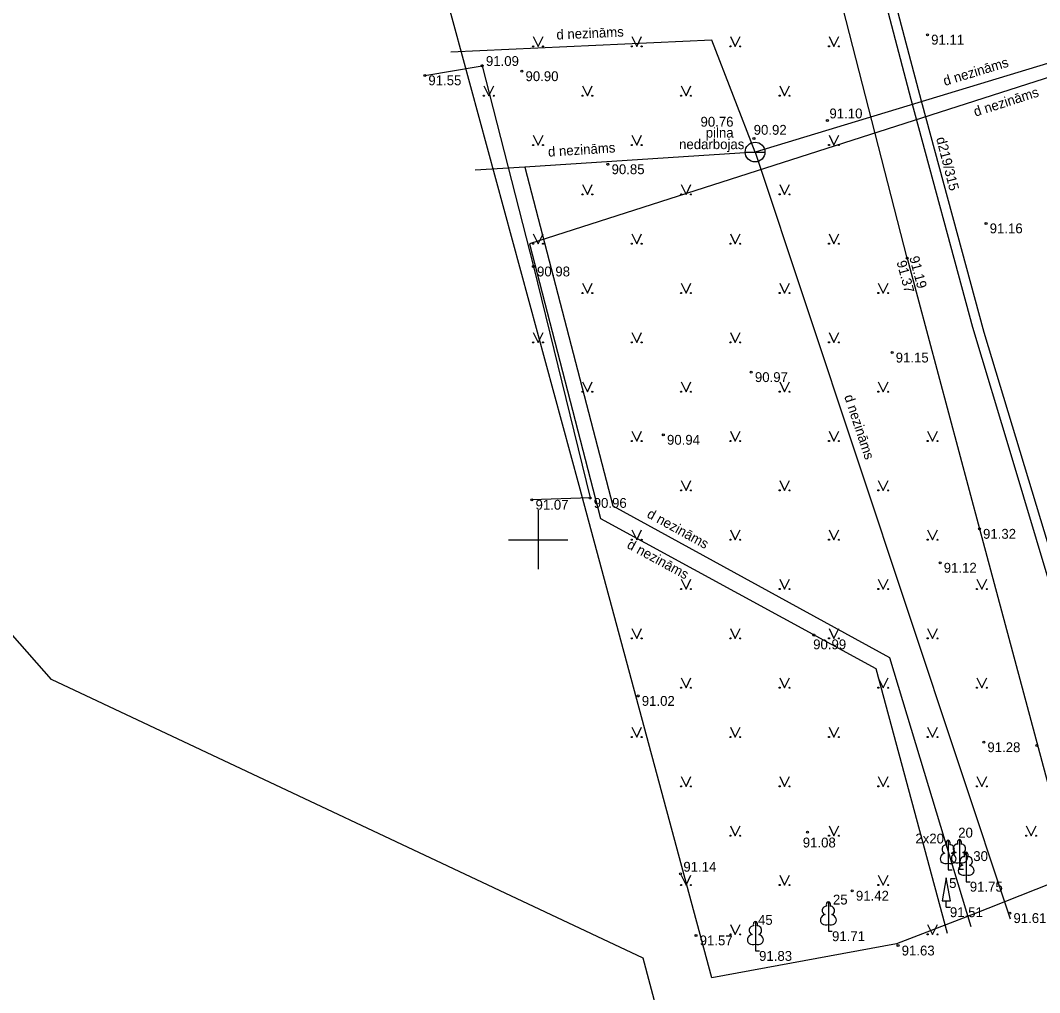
# Model space of a CAD drawing. Extents: x 634272 to 634544, y 247463 to 247653.
# Drawn here: x 634323.8 to 634375.4, y 247527 to 247576.3 of the extents above; entities that cross this region are included whole.
import ezdxf

# ---------------------------------------------------------------- set-up
doc = ezdxf.new("R2010")
doc.units = 0
for name, color, linetype in [('CELI_CAPM_####_####_#', 7, 'Continuous'), ('GEOD_ELEM_####_####_#', 7, 'Continuous'), ('NORB_ZOGS_ZSTP_####_#', 7, 'Continuous'), ('RAMI_UZMR_####_####_#', 7, 'Continuous'), ('RELJ_AATZ_####_TKST_#', 7, 'Continuous'), ('RELJ_ELEM_####_####_#', 7, 'Continuous'), ('ROBZ_PROJ_####_####_#', 7, 'Continuous'), ('SILT_VADP_UDEN_####_#', 7, 'Continuous'), ('SILT_VADP_UDEN_TKST_#', 7, 'Continuous'), ('TERT_DIAM_####_TKST_#', 7, 'Continuous'), ('TERT_ELEM_####_####_#', 7, 'Continuous'), ('UDTK_ELEM_####_####_#', 7, 'Continuous'), ('UDTK_ELEM_####_TKST_#', 7, 'Continuous'), ('UDTK_VADP_NEDR_####_#', 7, 'Continuous'), ('UDTK_VADP_NEDR_TKST_#', 7, 'Continuous')]:
    doc.layers.add(name, color=color, linetype=linetype)

msp = doc.modelspace()

# ---------------------------------------------------------------- linework, layer by layer
at = {"layer": 'CELI_CAPM_####_####_#'}
for points in [[(634368.714, 247564.266), (634363.359, 247585.148)], [(634368.714, 247564.266), (634372.374, 247550.548), (634376.283, 247536.001), (634382.231, 247537.822), (634388.468, 247539.583)]]:
    msp.add_lwpolyline(points, dxfattribs=at)
at = {"layer": 'GEOD_ELEM_####_####_#'}
for p, q in [((634350, 247551.5), (634350, 247550)), ((634348.5, 247550), (634350, 247550)), ((634350, 247550), (634350, 247548.5)), ((634350, 247550), (634351.5, 247550))]:
    msp.add_line(p, q, dxfattribs=at)
at = {"layer": 'NORB_ZOGS_ZSTP_####_#'}
msp.add_lwpolyline([(634344.251, 247573.53), (634347.163, 247574.022), (634349.76, 247563.843), (634352.634, 247552.114), (634349.684, 247552.021)], dxfattribs=at)
at = {"layer": 'RAMI_UZMR_####_####_#'}
msp.add_lwpolyline([(634376.048, 247532.596), (634371.988, 247530.992), (634368.176, 247529.515), (634358.81, 247527.799), (634352.082, 247552.749), (634342.787, 247586.946)], dxfattribs=at)
at = {"layer": 'RELJ_ELEM_####_####_#'}
for centre in [(634369.743, 247575.59), (634347.163, 247574.022), (634349.176, 247573.739), (634344.251, 247573.53), (634364.666, 247571.247), (634360.946, 247570.338), (634353.54, 247569.024), (634372.711, 247566.027), (634368.714, 247564.266), (634349.76, 247563.843), (634367.946, 247559.481), (634360.808, 247558.49), (634356.35, 247555.313), (634349.684, 247552.021), (634352.634, 247552.114), (634372.374, 247550.548), (634370.382, 247548.828), (634363.979, 247545.17), (634355.072, 247542.081), (634372.595, 247539.734), (634375.29, 247539.569), (634363.659, 247535.185), (634357.225, 247533.074), (634365.928, 247532.207), (634373.916, 247531.075), (634358.007, 247529.944), (634368.249, 247529.431)]:
    msp.add_circle(centre, 0.05, dxfattribs=at)
at = {"layer": 'ROBZ_PROJ_####_####_#'}
for points in [[(634325.336, 247542.912), (634316.666, 247552.747)], [(634355.331, 247528.803), (634325.336, 247542.912)], [(634358.525, 247516.788), (634355.331, 247528.803)]]:
    msp.add_lwpolyline(points, dxfattribs=at)
at = {"layer": 'SILT_VADP_UDEN_####_#'}
for points in [[(634363.886, 247593.437), (634366.36, 247583.831), (634369.421, 247572.245), (634372.593, 247560.517), (634376.47, 247547.723), (634378.808, 247540.177), (634380.88, 247533.487)], [(634380.38, 247533.332), (634378.785, 247538.524), (634375.914, 247547.864), (634373.98, 247554.308), (634372.046, 247560.751), (634368.919, 247572.314), (634365.801, 247584.167), (634363.457, 247593.328)]]:
    msp.add_lwpolyline(points, dxfattribs=at)
at = {"layer": 'TERT_ELEM_####_####_#'}
for p, q in [((634349.75, 247575.5), (634350, 247575)), ((634350, 247575), (634350.25, 247575.5)), ((634354.75, 247575.5), (634355, 247575)), ((634355, 247575), (634355.25, 247575.5)), ((634359.75, 247575.5), (634360, 247575)), ((634360, 247575), (634360.25, 247575.5)), ((634364.75, 247575.5), (634365, 247575)), ((634365, 247575), (634365.25, 247575.5)), ((634347.25, 247573), (634347.5, 247572.5)), ((634347.5, 247572.5), (634347.75, 247573)), ((634352.25, 247573), (634352.5, 247572.5)), ((634352.5, 247572.5), (634352.75, 247573)), ((634357.25, 247573), (634357.5, 247572.5)), ((634357.5, 247572.5), (634357.75, 247573)), ((634362.25, 247573), (634362.5, 247572.5)), ((634362.5, 247572.5), (634362.75, 247573)), ((634349.75, 247570.5), (634350, 247570)), ((634350, 247570), (634350.25, 247570.5)), ((634354.75, 247570.5), (634355, 247570)), ((634355, 247570), (634355.25, 247570.5)), ((634364.75, 247570.5), (634365, 247570)), ((634365, 247570), (634365.25, 247570.5)), ((634352.25, 247568), (634352.5, 247567.5)), ((634352.5, 247567.5), (634352.75, 247568)), ((634357.25, 247568), (634357.5, 247567.5)), ((634357.5, 247567.5), (634357.75, 247568)), ((634362.25, 247568), (634362.5, 247567.5)), ((634362.5, 247567.5), (634362.75, 247568)), ((634349.75, 247565.5), (634350, 247565)), ((634350, 247565), (634350.25, 247565.5)), ((634354.75, 247565.5), (634355, 247565)), ((634355, 247565), (634355.25, 247565.5)), ((634359.75, 247565.5), (634360, 247565)), ((634360, 247565), (634360.25, 247565.5)), ((634364.75, 247565.5), (634365, 247565)), ((634365, 247565), (634365.25, 247565.5)), ((634352.25, 247563), (634352.5, 247562.5)), ((634352.5, 247562.5), (634352.75, 247563)), ((634357.25, 247563), (634357.5, 247562.5)), ((634357.5, 247562.5), (634357.75, 247563)), ((634362.25, 247563), (634362.5, 247562.5)), ((634362.5, 247562.5), (634362.75, 247563)), ((634367.25, 247563), (634367.5, 247562.5)), ((634367.5, 247562.5), (634367.75, 247563)), ((634349.75, 247560.5), (634350, 247560)), ((634350, 247560), (634350.25, 247560.5)), ((634354.75, 247560.5), (634355, 247560)), ((634355, 247560), (634355.25, 247560.5)), ((634359.75, 247560.5), (634360, 247560)), ((634360, 247560), (634360.25, 247560.5)), ((634364.75, 247560.5), (634365, 247560)), ((634365, 247560), (634365.25, 247560.5)), ((634352.25, 247558), (634352.5, 247557.5)), ((634352.5, 247557.5), (634352.75, 247558)), ((634357.25, 247558), (634357.5, 247557.5)), ((634357.5, 247557.5), (634357.75, 247558)), ((634362.25, 247558), (634362.5, 247557.5)), ((634362.5, 247557.5), (634362.75, 247558)), ((634367.25, 247558), (634367.5, 247557.5)), ((634367.5, 247557.5), (634367.75, 247558)), ((634354.75, 247555.5), (634355, 247555)), ((634355, 247555), (634355.25, 247555.5)), ((634359.75, 247555.5), (634360, 247555)), ((634360, 247555), (634360.25, 247555.5)), ((634364.75, 247555.5), (634365, 247555)), ((634365, 247555), (634365.25, 247555.5)), ((634369.75, 247555.5), (634370, 247555)), ((634370, 247555), (634370.25, 247555.5)), ((634357.25, 247553), (634357.5, 247552.5)), ((634357.5, 247552.5), (634357.75, 247553)), ((634362.25, 247553), (634362.5, 247552.5)), ((634362.5, 247552.5), (634362.75, 247553)), ((634367.25, 247553), (634367.5, 247552.5)), ((634367.5, 247552.5), (634367.75, 247553)), ((634354.75, 247550.5), (634355, 247550)), ((634355, 247550), (634355.25, 247550.5)), ((634359.75, 247550.5), (634360, 247550)), ((634360, 247550), (634360.25, 247550.5)), ((634364.75, 247550.5), (634365, 247550)), ((634365, 247550), (634365.25, 247550.5)), ((634369.75, 247550.5), (634370, 247550)), ((634370, 247550), (634370.25, 247550.5)), ((634357.25, 247548), (634357.5, 247547.5)), ((634357.5, 247547.5), (634357.75, 247548)), ((634362.25, 247548), (634362.5, 247547.5)), ((634362.5, 247547.5), (634362.75, 247548)), ((634367.25, 247548), (634367.5, 247547.5)), ((634367.5, 247547.5), (634367.75, 247548)), ((634372.25, 247548), (634372.5, 247547.5)), ((634372.5, 247547.5), (634372.75, 247548)), ((634354.75, 247545.5), (634355, 247545)), ((634355, 247545), (634355.25, 247545.5)), ((634359.75, 247545.5), (634360, 247545)), ((634360, 247545), (634360.25, 247545.5)), ((634364.75, 247545.5), (634365, 247545)), ((634365, 247545), (634365.25, 247545.5)), ((634369.75, 247545.5), (634370, 247545)), ((634370, 247545), (634370.25, 247545.5)), ((634357.25, 247543), (634357.5, 247542.5)), ((634357.5, 247542.5), (634357.75, 247543)), ((634362.25, 247543), (634362.5, 247542.5)), ((634362.5, 247542.5), (634362.75, 247543)), ((634367.25, 247543), (634367.5, 247542.5)), ((634367.5, 247542.5), (634367.75, 247543)), ((634372.25, 247543), (634372.5, 247542.5)), ((634372.5, 247542.5), (634372.75, 247543)), ((634354.75, 247540.5), (634355, 247540)), ((634355, 247540), (634355.25, 247540.5)), ((634359.75, 247540.5), (634360, 247540)), ((634360, 247540), (634360.25, 247540.5)), ((634364.75, 247540.5), (634365, 247540)), ((634365, 247540), (634365.25, 247540.5)), ((634369.75, 247540.5), (634370, 247540)), ((634370, 247540), (634370.25, 247540.5)), ((634357.25, 247538), (634357.5, 247537.5)), ((634357.5, 247537.5), (634357.75, 247538)), ((634362.25, 247538), (634362.5, 247537.5)), ((634362.5, 247537.5), (634362.75, 247538)), ((634367.25, 247538), (634367.5, 247537.5)), ((634367.5, 247537.5), (634367.75, 247538)), ((634372.25, 247538), (634372.5, 247537.5)), ((634372.5, 247537.5), (634372.75, 247538)), ((634359.75, 247535.5), (634360, 247535)), ((634360, 247535), (634360.25, 247535.5)), ((634364.75, 247535.5), (634365, 247535)), ((634365, 247535), (634365.25, 247535.5)), ((634374.75, 247535.5), (634375, 247535)), ((634375, 247535), (634375.25, 247535.5)), ((634370.791, 247533.613), (634370.791, 247533.266)), ((634371.363, 247533.647), (634371.363, 247533.3)), ((634357.25, 247533), (634357.5, 247532.5)), ((634357.5, 247532.5), (634357.75, 247533)), ((634362.25, 247533), (634362.5, 247532.5)), ((634362.5, 247532.5), (634362.75, 247533)), ((634367.25, 247533), (634367.5, 247532.5)), ((634367.5, 247532.5), (634367.75, 247533)), ((634370.791, 247533.266), (634370.991, 247533.266)), ((634371.363, 247533.3), (634371.563, 247533.3)), ((634371.703, 247533.014), (634371.703, 247532.667)), ((634371.703, 247532.667), (634371.903, 247532.667)), ((634370.693, 247531.373), (634370.693, 247531.693)), ((634370.693, 247531.373), (634370.903, 247531.373)), ((634359.75, 247530.5), (634360, 247530)), ((634360, 247530), (634360.25, 247530.5)), ((634364.718, 247530.504), (634364.718, 247530.157)), ((634369.75, 247530.5), (634370, 247530)), ((634370, 247530), (634370.25, 247530.5)), ((634364.718, 247530.157), (634364.918, 247530.157)), ((634361.019, 247529.506), (634361.019, 247529.159)), ((634361.019, 247529.159), (634361.219, 247529.159))]:
    msp.add_line(p, q, dxfattribs=at)
for points in [[(634370.791, 247534.766), (634370.791, 247533.613)], [(634370.881, 247534.534), (634370.88, 247534.535)], [(634371.363, 247534.8), (634371.363, 247533.647)], [(634371.453, 247534.568), (634371.452, 247534.569)], [(634371.703, 247534.167), (634371.703, 247533.014)], [(634371.793, 247533.935), (634371.792, 247533.936)], [(634364.718, 247531.657), (634364.718, 247530.504)], [(634364.808, 247531.425), (634364.807, 247531.426)], [(634361.019, 247530.659), (634361.019, 247529.506)], [(634361.109, 247530.427), (634361.108, 247530.428)]]:
    msp.add_lwpolyline(points, dxfattribs=at)
msp.add_lwpolyline([(634370.483, 247531.693), (634370.903, 247531.693), (634370.693, 247532.873)], close=True, dxfattribs=at)
for centre, radius in [((634349.75, 247575), 0.028), ((634350.25, 247575), 0.0263), ((634354.75, 247575), 0.028), ((634355.25, 247575), 0.0263), ((634359.75, 247575), 0.028), ((634360.25, 247575), 0.0263), ((634364.75, 247575), 0.028), ((634365.25, 247575), 0.0263), ((634347.25, 247572.5), 0.028), ((634347.75, 247572.5), 0.0263), ((634352.25, 247572.5), 0.028), ((634352.75, 247572.5), 0.0263), ((634357.25, 247572.5), 0.028), ((634357.75, 247572.5), 0.0263), ((634362.25, 247572.5), 0.028), ((634362.75, 247572.5), 0.0263), ((634349.75, 247570), 0.028), ((634350.25, 247570), 0.0263), ((634354.75, 247570), 0.028), ((634355.25, 247570), 0.0263), ((634364.75, 247570), 0.028), ((634365.25, 247570), 0.0263), ((634352.25, 247567.5), 0.028), ((634352.75, 247567.5), 0.0263), ((634357.25, 247567.5), 0.028), ((634357.75, 247567.5), 0.0263), ((634362.25, 247567.5), 0.028), ((634362.75, 247567.5), 0.0263), ((634349.75, 247565), 0.028), ((634350.25, 247565), 0.0263), ((634354.75, 247565), 0.028), ((634355.25, 247565), 0.0263), ((634359.75, 247565), 0.028), ((634360.25, 247565), 0.0263), ((634364.75, 247565), 0.028), ((634365.25, 247565), 0.0263), ((634352.25, 247562.5), 0.028), ((634352.75, 247562.5), 0.0263), ((634357.25, 247562.5), 0.028), ((634357.75, 247562.5), 0.0263), ((634362.25, 247562.5), 0.028), ((634362.75, 247562.5), 0.0263), ((634367.25, 247562.5), 0.028), ((634367.75, 247562.5), 0.0263), ((634349.75, 247560), 0.028), ((634350.25, 247560), 0.0263), ((634354.75, 247560), 0.028), ((634355.25, 247560), 0.0263), ((634359.75, 247560), 0.028), ((634360.25, 247560), 0.0263), ((634364.75, 247560), 0.028), ((634365.25, 247560), 0.0263), ((634352.25, 247557.5), 0.028), ((634352.75, 247557.5), 0.0263), ((634357.25, 247557.5), 0.028), ((634357.75, 247557.5), 0.0263), ((634362.25, 247557.5), 0.028), ((634362.75, 247557.5), 0.0263), ((634367.25, 247557.5), 0.028), ((634367.75, 247557.5), 0.0263), ((634354.75, 247555), 0.028), ((634355.25, 247555), 0.0263), ((634359.75, 247555), 0.028), ((634360.25, 247555), 0.0263), ((634364.75, 247555), 0.028), ((634365.25, 247555), 0.0263), ((634369.75, 247555), 0.028), ((634370.25, 247555), 0.0263), ((634357.25, 247552.5), 0.028), ((634357.75, 247552.5), 0.0263), ((634362.25, 247552.5), 0.028), ((634362.75, 247552.5), 0.0263), ((634367.25, 247552.5), 0.028), ((634367.75, 247552.5), 0.0263), ((634354.75, 247550), 0.028), ((634355.25, 247550), 0.0263), ((634359.75, 247550), 0.028), ((634360.25, 247550), 0.0263), ((634364.75, 247550), 0.028), ((634365.25, 247550), 0.0263), ((634369.75, 247550), 0.028), ((634370.25, 247550), 0.0263), ((634357.25, 247547.5), 0.028), ((634357.75, 247547.5), 0.0263), ((634362.25, 247547.5), 0.028), ((634362.75, 247547.5), 0.0263), ((634367.25, 247547.5), 0.028), ((634367.75, 247547.5), 0.0263), ((634372.25, 247547.5), 0.028), ((634372.75, 247547.5), 0.0263), ((634354.75, 247545), 0.028), ((634355.25, 247545), 0.0263), ((634359.75, 247545), 0.028), ((634360.25, 247545), 0.0263), ((634364.75, 247545), 0.028), ((634365.25, 247545), 0.0263), ((634369.75, 247545), 0.028), ((634370.25, 247545), 0.0263), ((634357.25, 247542.5), 0.028), ((634357.75, 247542.5), 0.0263), ((634362.25, 247542.5), 0.028), ((634362.75, 247542.5), 0.0263), ((634367.25, 247542.5), 0.028), ((634367.75, 247542.5), 0.0263), ((634372.25, 247542.5), 0.028), ((634372.75, 247542.5), 0.0263), ((634354.75, 247540), 0.028), ((634355.25, 247540), 0.0263), ((634359.75, 247540), 0.028), ((634360.25, 247540), 0.0263), ((634364.75, 247540), 0.028), ((634365.25, 247540), 0.0263), ((634369.75, 247540), 0.028), ((634370.25, 247540), 0.0263), ((634357.25, 247537.5), 0.028), ((634357.75, 247537.5), 0.0263), ((634362.25, 247537.5), 0.028), ((634362.75, 247537.5), 0.0263), ((634367.25, 247537.5), 0.028), ((634367.75, 247537.5), 0.0263), ((634372.25, 247537.5), 0.028), ((634372.75, 247537.5), 0.0263), ((634359.75, 247535), 0.028), ((634360.25, 247535), 0.0263), ((634364.75, 247535), 0.028), ((634365.25, 247535), 0.0263), ((634374.75, 247535), 0.028), ((634375.25, 247535), 0.0263), ((634357.25, 247532.5), 0.028), ((634357.75, 247532.5), 0.0263), ((634362.25, 247532.5), 0.028), ((634362.75, 247532.5), 0.0263), ((634367.25, 247532.5), 0.028), ((634367.75, 247532.5), 0.0263), ((634359.75, 247530), 0.028), ((634360.25, 247530), 0.0263), ((634369.75, 247530), 0.028), ((634370.25, 247530), 0.0263)]:
    msp.add_circle(centre, radius, dxfattribs=at)
for centre, major_axis, ratio, start_param, end_param in [((634370.663, 247534.321), (-0.039, -0.212), 0.861323, 3.141593, 6.283185), ((634370.791, 247534.616), (0, -0.15), 0.707107, 3.14537, 5.287485), ((634370.791, 247534.616), (0, -0.15), 0.707107, 0.995701, 3.137816), ((634370.919, 247534.321), (0.039, -0.212), 0.861323, 0, 3.141593), ((634371.235, 247534.355), (-0.039, -0.212), 0.861323, 3.141593, 6.283185), ((634371.363, 247534.65), (0, -0.15), 0.707107, 3.14537, 5.287485), ((634371.363, 247534.65), (0, -0.15), 0.707107, 0.995701, 3.137816), ((634371.491, 247534.355), (0.039, -0.212), 0.861323, 0, 3.141593), ((634370.701, 247533.859), (0.307, 0.095), 0.814445, 1.570796, 4.752015), ((634370.881, 247533.859), (-0.307, 0.095), 0.814445, 1.531171, 4.712389), ((634371.273, 247533.893), (0.307, 0.095), 0.814445, 1.570796, 4.752015), ((634371.453, 247533.893), (-0.307, 0.095), 0.814445, 1.531171, 4.712389), ((634371.703, 247534.017), (0, -0.15), 0.707107, 3.14537, 5.287485), ((634371.703, 247534.017), (0, -0.15), 0.707107, 0.995701, 3.137816), ((634371.613, 247533.26), (0.307, 0.095), 0.814445, 1.570796, 4.752015), ((634371.575, 247533.722), (-0.039, -0.212), 0.861323, 3.141593, 6.283185), ((634371.793, 247533.26), (-0.307, 0.095), 0.814445, 1.531171, 4.712389), ((634371.831, 247533.722), (0.039, -0.212), 0.861323, 0, 3.141593), ((634364.59, 247531.212), (-0.039, -0.212), 0.861323, 3.141593, 6.283185), ((634364.718, 247531.507), (0, -0.15), 0.707107, 3.14537, 5.287485), ((634364.718, 247531.507), (0, -0.15), 0.707107, 0.995701, 3.137816), ((634364.846, 247531.212), (0.039, -0.212), 0.861323, 0, 3.141593), ((634364.628, 247530.75), (0.307, 0.095), 0.814445, 1.570796, 4.752015), ((634364.808, 247530.75), (-0.307, 0.095), 0.814445, 1.531171, 4.712389), ((634360.891, 247530.214), (-0.039, -0.212), 0.861323, 3.141593, 6.283185), ((634361.019, 247530.509), (0, -0.15), 0.707107, 3.14537, 5.287485), ((634361.019, 247530.509), (0, -0.15), 0.707107, 0.995701, 3.137816), ((634361.147, 247530.214), (0.039, -0.212), 0.861323, 0, 3.141593), ((634360.929, 247529.752), (0.307, 0.095), 0.814445, 1.570796, 4.752015), ((634361.109, 247529.752), (-0.307, 0.095), 0.814445, 1.531171, 4.712389)]:
    msp.add_ellipse(centre, major_axis=major_axis, ratio=ratio, start_param=start_param, end_param=end_param, dxfattribs=at)
at = {"layer": 'UDTK_ELEM_####_####_#'}
msp.add_line((634360.501, 247569.644), (634361.501, 247569.644), dxfattribs=at)
msp.add_circle((634361.001, 247569.644), 0.5, dxfattribs=at)
at = {"layer": 'UDTK_VADP_NEDR_####_#'}
for points in [[(634381.084, 247599.023), (634386.736, 247576.903), (634349.56, 247564.99), (634353.161, 247551.069), (634367.117, 247543.476), (634370.735, 247530.054)], [(634380.607, 247598.87), (634386.132, 247577.25), (634361, 247569.644)], [(634361, 247569.644), (634358.801, 247575.311), (634345.573, 247574.703)], [(634361, 247569.644), (634349.33, 247568.879), (634346.818, 247568.73)], [(634361, 247569.644), (634373.937, 247530.786)], [(634349.33, 247568.879), (634353.79, 247551.722), (634367.819, 247544.026), (634371.947, 247530.397)]]:
    msp.add_lwpolyline(points, dxfattribs=at)

# ---------------------------------------------------------------- texts
at = {"layer": 'RELJ_AATZ_####_TKST_#'}
for s, p in [(' 91.11', (634369.743, 247575.09)), (' 91.09', (634347.169, 247574.007)), (' 91.55', (634344.251, 247573.03)), (' 90.90', (634349.176, 247573.239)), (' 91.10', (634364.586, 247571.351)), (' 90.92', (634360.745, 247570.521)), (' 90.85', (634353.54, 247568.524)), (' 91.16', (634372.711, 247565.527)), (' 90.98', (634349.76, 247563.343)), (' 91.15', (634367.946, 247558.981)), (' 90.97', (634360.808, 247557.99)), (' 90.94', (634356.35, 247554.813)), (' 90.96', (634352.634, 247551.614)), (' 91.07', (634349.684, 247551.521)), (' 91.32', (634372.374, 247550.048)), (' 91.12', (634370.382, 247548.328)), (' 90.99', (634363.761, 247544.447)), (' 91.02', (634355.072, 247541.581)), (' 91.28', (634372.595, 247539.234)), (' 91.08', (634363.235, 247534.405)), (' 91.14', (634357.18, 247533.176)), (' 91.75', (634371.703, 247532.167)), (' 91.42', (634365.928, 247531.707)), (' 91.51', (634370.693, 247530.873)), (' 91.51', (634370.693, 247530.873)), (' 91.61', (634373.916, 247530.575)), (' 91.57', (634358.007, 247529.444)), (' 91.71', (634364.718, 247529.657)), (' 91.63', (634368.249, 247528.931)), (' 91.83', (634361.019, 247528.659))]:
    msp.add_text(s, height=0.5, dxfattribs=at).set_placement(p)
for s, p in [(' 91.37', (634368.122, 247564.257)), (' 91.19', (634368.767, 247564.483))]:
    msp.add_text(s, height=0.5, rotation=284.9387, dxfattribs=at).set_placement(p)
at = {"layer": 'SILT_VADP_UDEN_TKST_#'}
msp.add_text('d219/315', height=0.5, rotation=284.4431, dxfattribs=at).set_placement((634370.178, 247570.342))
at = {"layer": 'TERT_DIAM_####_TKST_#'}
for s, p in [('2x20', (634369.129, 247534.606)), ('20', (634371.301, 247534.904)), ('30', (634372.065, 247533.716)), ('5', (634370.841, 247532.349)), ('25', (634364.949, 247531.514)), ('45', (634361.151, 247530.484))]:
    msp.add_text(s, height=0.5, dxfattribs=at).set_placement(p)
at = {"layer": 'UDTK_ELEM_####_TKST_#'}
for s, p in [(' 90.76', (634358.049, 247570.931)), ('pilna ', (634358.5, 247570.378)), ('nedarbojas', (634357.148, 247569.793))]:
    msp.add_text(s, height=0.5, dxfattribs=at).set_placement(p)
at = {"layer": 'UDTK_VADP_NEDR_TKST_#'}
for rotation, p in [(2.6324, (634350.939, 247575.345)), (16.838, (634370.625, 247572.994)), (17.768, (634372.175, 247571.433)), (3.7505, (634350.518, 247569.408)), (288.4143, (634365.512, 247557.261)), (331.2518, (634355.475, 247551.163)), (331.4517, (634354.462, 247549.606))]:
    msp.add_text('d nezināms', height=0.5, rotation=rotation, dxfattribs=at).set_placement(p)

doc.saveas('drawing.dxf')
